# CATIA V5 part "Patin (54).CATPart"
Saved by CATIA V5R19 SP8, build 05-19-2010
Part number: Patin (54)
Nomenclature: 54
Material "Caoutchouc": density 910 kg/m3, Young's modulus 2e+06 Pa, Poisson ratio 0.49, thermal expansion 0.000162 1/K
Material "Acier": density 7860 kg/m3, Young's modulus 2e+11 Pa, Poisson ratio 0.266, thermal expansion 1.17e-05 1/K
Bounding box of the stored display mesh (mm): x -20 to 20, y -20 to 20, z 0 to 35
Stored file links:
  C:\Users\rphgr\Desktop\0_Tapis_TC520B_vitesse\Patin (54).CATPart
  D:\Programmes\DassaultSysteme\win_b64\startup\materials\French\Catalog.CATMaterial
  C:\Program Files\Dassault Systemes\B19\win_b64\reffiles\standard\MetricThickPitch.txt
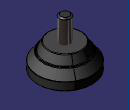
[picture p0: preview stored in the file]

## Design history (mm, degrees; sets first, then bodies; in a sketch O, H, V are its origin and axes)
AxisSystem1: origin (0, 0, 0), X (1, 0, 0), Y (0, 1, 0), Z (0, 0, 1)
Body1 (main body), material "Caoutchouc"
  Sketch1 on YZ plane of AxisSystem1, origin (0, 0, 0), H (0, 1, 0), V (0, 0, 1)
    point P1 (0, 18)
    line L1 (0, 18) -> (12, 18)
    point P2 (12, 18)
    line L2 (12, 18) -> (14.7988, 12)
    line L3 (14.7988, 12) -> (15.7988, 12)
    line L4 (15.7988, 12) -> (20, 6)
    line L5 (20, 6) -> (20, 0)
    line L6 (15.7002, 0) -> (15, 1)
    point P7 (15, 1)
    line L7 (15, 1) -> (14.2998, 0)
    point P8 (7.7002, 0)
    line L8 (7.7002, 0) -> (7, 1)
    point P9 (7, 1)
    line L9 (7, 1) -> (6.2998, 0)
    axis line L10 (0, 164.7026) -> (0, 0)
    point P11 (0, 164.7026)
    reference intersected line E1 through (0, 0) direction (-1, 0) from XY plane of AxisSystem1
    reference projected line E2 through (0, 0) direction (0, 1) from edge [ZX plane of AxisSystem1 | YZ plane of AxisSystem1]
    line L11 (0, 0) -> (6.2998, 0)
    point P12 (7.7002, 0)
    line L12 (7.7002, 0) -> (14.2998, 0)
    line L13 (15.7002, 0) -> (20, 0)
    reference intersected line E3 through (0, 0) direction (-1, 0) from XY plane of AxisSystem1
    reference intersected line E4 through (0, 0) direction (-1, 0) from XY plane of AxisSystem1
    angle L4 E1 = 55
    distance P9 E2 = 7
    distance P7 P9 H = 8
    "Radius" L5 L10 = 20
    distance L3 E3 = 12
    distance L1 E4 = 18
    length L5 = 6
    "Radius" P2 L10 = 12
    length L3 = 1
    angle L13 L7 = 55
    distance P7 L13 = 1
    distance P9 L12 = 1
    horizontal: L1 H, L3 H, L11 H, L12 H, L13 H
    vertical: L5 V, L10 V
    parallelism: L8 L6, L9 L7, L6 L4
    coincidence: P11 V, L13 L12, L12 L11, P8 P12, P1 L10, O L11
  Shaft1: profile Sketch1, axis Sketch1.L10, angle 360
  Fillet1: radius 0.5, on face of Shaft1 from Sketch1.L2; face of Shaft1 from Sketch1.L4; face of Shaft1 from Sketch1.L5; face of Shaft1 from Sketch1.L9; face of Shaft1 from Sketch1.L8; face of Shaft1 from Sketch1.L7; face of Shaft1 from Sketch1.L6
Body2 "Vis", material "Acier"
  Sketch2 on YZ plane of AxisSystem1, origin (0, 0, 0), H (0, 1, 0), V (0, 0, 1)
    point P1 (0, 35)
    line L1 (0, 35) -> (-4, 35)
    line L2 (-4, 35) -> (-4, 12)
    line L3 (-4, 12) -> (-7.5, 12)
    line L4 (-7.5, 12) -> (-7.5, 7)
    line L5 (-7.5, 7) -> (0, 7)
    point P6 (0, 7)
    axis line L6 (0, 34.6469) -> (0, -4.1848)
    point P7 (0, 34.6469)
    distance L5 L1 = 28
    distance L3 L5 = 5
    distance L4 L6 = 7.5
    distance L2 L6 = 4
    distance L1 H = 35
    coincidence: P1 V, P6 V, P7 V
    horizontal: L1 H, L3 H, L5 H
    vertical: L2 V, L4 V, L6 V
  Shaft2: profile Sketch2, axis Sketch2.L6, angle 360
  Thread1: "M8", diameter 8, depth 23, pitch 1.25, on face of Shaft2 from Sketch2.L2, from face of Shaft2 from Sketch2.L1
  Chamfer1: length 1, angle 45, on edge [face of Shaft2 from Sketch2.L1 | face of Shaft2 from Sketch2.L2]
